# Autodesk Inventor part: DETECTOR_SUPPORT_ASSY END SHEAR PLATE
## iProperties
Shininess: 64.0
Length Units: 11272
Angle Units: 11279
Time Units: 11290
Mass Units: 11286
Length Display Precision: 3
Angle Display Precision: 2
Compacted: True
Part Number: DETECTOR_SUPPORT_ASSY END SHEAR PLATE
Document SubType Name: Modeling
Created: 2004-08
Designer: John Blackburn
Material: ALUMINUM
Manufacturer: Standard
Standards Organization: Custom
Density: 0.0
Volumn: 0.0
Area: 0.0
PropertySet Name: Model Information
Control State: 0
Master: False
Checked Out: False
Author: John Blackburn
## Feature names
1. ExtrusionBlind1
2. Hole1
3. Hole2
4. Hole3
5. Hole4
6. Hole5
7. Hole6
